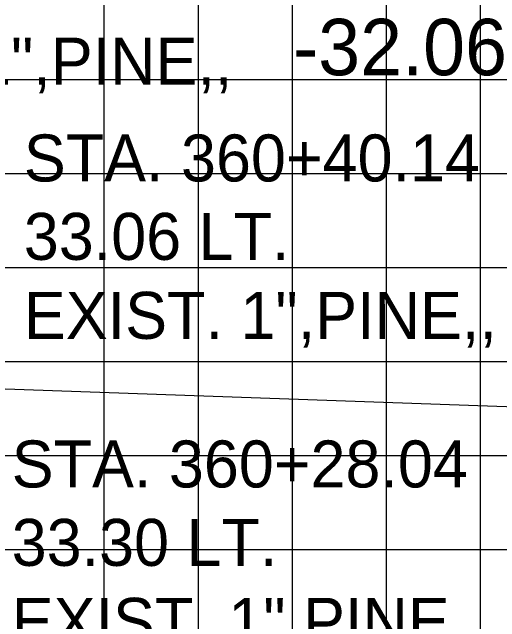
# Model space of a CAD drawing. Extents: x 1146525 to 1146695, y 608981 to 609091.
# Drawn here: x 1146566.69 to 1146571.88, y 608996.57 to 609003.05 of the extents above; entities that cross this region are included whole.
import ezdxf

# ---------------------------------------------------------------- set-up
doc = ezdxf.new("R2010")
doc.units = 0
for name, color, linetype in [('D_Text_Monospaced', 7, 'Continuous'), ('D_Text_Standard', 7, 'Continuous'), ('MAJOR', 7, 'Continuous'), ('MINOR', 7, 'Continuous'), ('S_Roadway_Centerline', 7, 'Continuous')]:
    doc.layers.add(name, color=color, linetype=linetype)

msp = doc.modelspace()

# ---------------------------------------------------------------- linework, layer by layer
at = {"layer": 'MAJOR'}
for p, q in [((1146567.6713, 608990.3351), (1146567.6713, 609010.3351)), ((1146537.6713, 609000.3351), (1146677.6713, 609000.3351))]:
    msp.add_line(p, q, dxfattribs=at)
at = {"layer": 'MINOR'}
for p, q in [((1146568.6713, 608990.3351), (1146568.6713, 609010.3351)), ((1146569.6713, 608990.3351), (1146569.6713, 609010.3351)), ((1146570.6713, 608990.3351), (1146570.6713, 609010.3351)), ((1146571.6713, 608990.3351), (1146571.6713, 609010.3351)), ((1146537.6713, 609002.3351), (1146677.6713, 609002.3351)), ((1146537.6713, 609001.3351), (1146677.6713, 609001.3351)), ((1146537.6713, 608999.3351), (1146677.6713, 608999.3351)), ((1146537.6713, 608998.3351), (1146677.6713, 608998.3351)), ((1146537.6713, 608997.3351), (1146677.6713, 608997.3351))]:
    msp.add_line(p, q, dxfattribs=at)
at = {"layer": 'S_Roadway_Centerline'}
msp.add_lwpolyline([(1146558.9716, 608999.3247), (1146561.0836, 608999.2405), (1146581.4003, 608998.5255), (1146588.8095, 608997.7067), (1146588.8622, 608997.6981), (1146592.9793, 608998.7563), (1146592.9882, 608998.7585), (1146592.9931, 608998.7584), (1146594.9072, 608998.7567), (1146601.6604, 608998.9113), (1146606.0944, 608999.0696), (1146612.7625, 608998.8478), (1146617.0979, 608998.7004), (1146618.9026, 608998.5325), (1146621.3021, 608998.3634), (1146623.6256, 608997.3107), (1146624.9189, 608996.8894), (1146629.6594, 608997.697), (1146630.2429, 608997.884), (1146632.1509, 608997.9905), (1146654.8098, 608998.7356), (1146655.9317, 608998.7799), (1146656.0934, 608998.7819)], dxfattribs=at)

# ---------------------------------------------------------------- texts
at = {"layer": 'D_Text_Monospaced'}
for s, p in [('EXIST. 1",PINE,,', (1146564.0033, 609002.2811)), ('STA. 360+40.14', (1146566.8151, 609001.2512)), ('33.06 LT.', (1146566.8151, 609000.4172)), ('EXIST. 1",PINE,,', (1146566.8151, 608999.5772)), ('STA. 360+28.04', (1146566.6861, 608997.9963)), ('33.30 LT.', (1146566.6861, 608997.1623)), ('EXIST. 1",PINE,,', (1146566.6861, 608996.3223))]:
    msp.add_text(s, height=0.49998, dxfattribs=at).set_placement(p)
at = {"layer": 'D_Text_Standard'}
msp.add_text('-32.06 FT', height=0.6, dxfattribs=at).set_placement((1146569.6787, 609002.3812))

doc.saveas('drawing.dxf')
